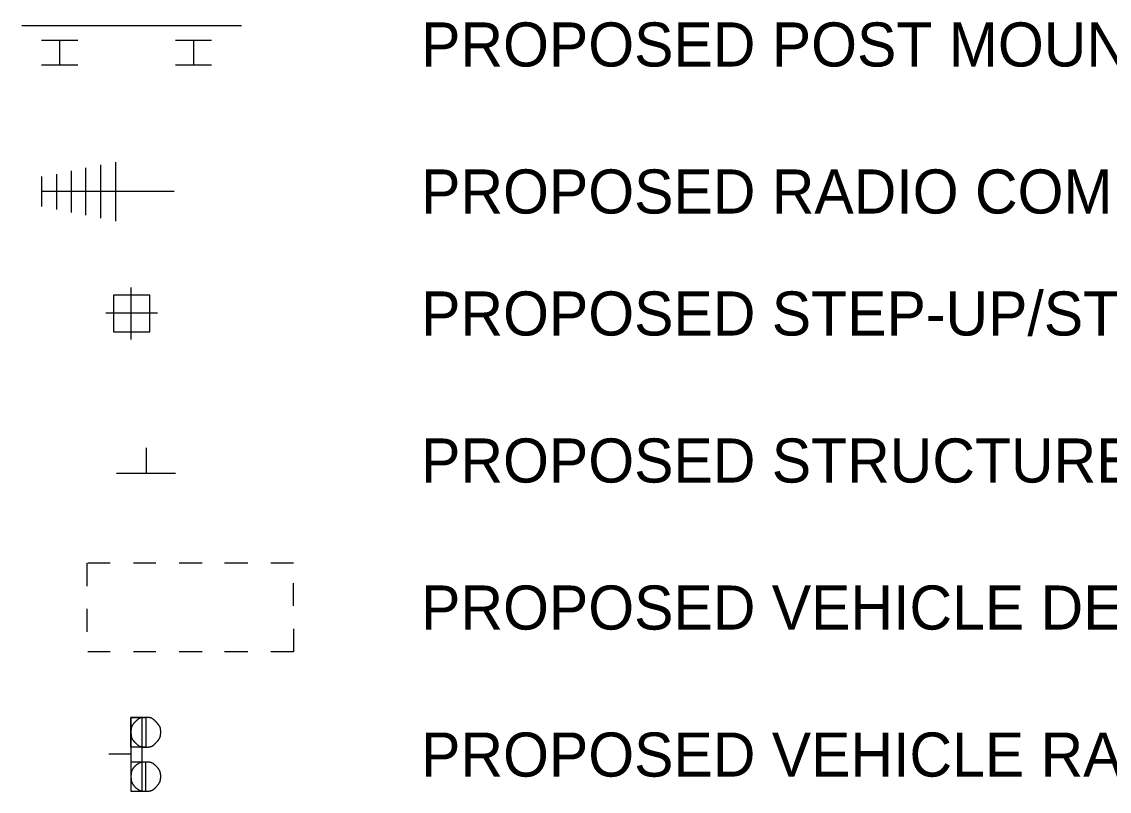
# Model space of a CAD drawing. Extents: x 1299104.8 to 1299141.6, y 239639.8 to 239661.8.
# Drawn here: x 1299113.684 to 1299116.643, y 239651.943 to 239654.037 of the extents above; entities that cross this region are included whole.
import ezdxf

# ---------------------------------------------------------------- set-up
doc = ezdxf.new("R2010")
doc.units = 0
for name, color, linetype in [('DIM TXT', 7, 'Continuous'), ('PDF2_Geometry', 7, 'Continuous'), ('PDF2_Solid Fills', 7, 'Continuous'), ('PDF3_Geometry', 7, 'Continuous'), ('PDF_LEGEND', 7, 'Continuous')]:
    doc.layers.add(name, color=color, linetype=linetype)

msp = doc.modelspace()

# ---------------------------------------------------------------- linework, layer by layer
at = {"layer": 'PDF2_Geometry'}
for points in [[(1299113.858, 239653.6389), (1299113.858, 239653.5105)], [(1299113.8985, 239653.6473), (1299113.8985, 239653.5022)], [(1299113.9389, 239653.6543), (1299113.9389, 239653.4938)], [(1299113.738, 239653.6152), (1299113.738, 239653.5343)], [(1299113.7785, 239653.6222), (1299113.7785, 239653.5259)], [(1299113.8189, 239653.6305), (1299113.8189, 239653.5175)], [(1299114.0994, 239653.5747), (1299113.738, 239653.5747)], [(1299114.0231, 239652.8777), (1299114.0231, 239652.8079)], [(1299114.1026, 239652.8079), (1299113.9422, 239652.8079)], [(1299113.8609, 239652.5634), (1299113.8609, 239652.5007)], [(1299113.9251, 239652.5634), (1299113.8637, 239652.5634)], [(1299114.0493, 239652.5634), (1299113.9879, 239652.5634)], [(1299114.1749, 239652.5634), (1299114.1121, 239652.5634)], [(1299114.2991, 239652.5634), (1299114.2363, 239652.5634)], [(1299114.4232, 239652.5634), (1299114.3618, 239652.5634)], [(1299114.4232, 239652.4476), (1299114.4232, 239652.509)], [(1299113.8609, 239652.4393), (1299113.8609, 239652.3765)], [(1299114.4232, 239652.3848), (1299114.4232, 239652.3221), (1299114.3618, 239652.3221)], [(1299113.9251, 239652.3221), (1299113.8637, 239652.3221)], [(1299114.0493, 239652.3221), (1299113.9879, 239652.3221)], [(1299114.1749, 239652.3221), (1299114.1121, 239652.3221)], [(1299114.2991, 239652.3221), (1299114.2363, 239652.3221)], [(1299113.9814, 239652.1439), (1299114.0121, 239652.1439)], [(1299113.9814, 239652.0435), (1299113.9214, 239652.0435)]]:
    msp.add_lwpolyline(points, dxfattribs=at)
for points in [[(1299113.9926, 239652.1314), (1299113.9856, 239652.1244), (1299113.9814, 239652.1146), (1299113.9814, 239652.1034)], [(1299114.0219, 239652.1439), (1299114.0107, 239652.1439), (1299114.001, 239652.1397), (1299113.9926, 239652.1314)], [(1299114.0498, 239652.1314), (1299114.0428, 239652.1397), (1299114.0317, 239652.1439), (1299114.0219, 239652.1439)], [(1299114.0624, 239652.1034), (1299114.0624, 239652.1146), (1299114.0568, 239652.1244), (1299114.0498, 239652.1314)], [(1299113.9814, 239652.1034), (1299113.9814, 239652.0923), (1299113.9856, 239652.0825), (1299113.9926, 239652.0755)], [(1299114.0498, 239652.0755), (1299114.0568, 239652.0825), (1299114.0624, 239652.0923), (1299114.0624, 239652.1034)], [(1299113.9926, 239652.0755), (1299114.001, 239652.0672), (1299114.0107, 239652.063), (1299114.0219, 239652.063)], [(1299114.0219, 239652.063), (1299114.0317, 239652.063), (1299114.0428, 239652.0672), (1299114.0498, 239652.0755)], [(1299113.9926, 239652.0114), (1299113.9856, 239652.0044), (1299113.9814, 239651.9932), (1299113.9814, 239651.9835)], [(1299114.0219, 239652.0225), (1299114.0107, 239652.0225), (1299114.001, 239652.0183), (1299113.9926, 239652.0114)], [(1299114.0498, 239652.0114), (1299114.0428, 239652.0183), (1299114.0317, 239652.0225), (1299114.0219, 239652.0225)], [(1299114.0624, 239651.9835), (1299114.0624, 239651.9932), (1299114.0568, 239652.0044), (1299114.0498, 239652.0114)], [(1299113.9814, 239651.9835), (1299113.9814, 239651.9723), (1299113.9856, 239651.9625), (1299113.9926, 239651.9542)], [(1299114.0498, 239651.9542), (1299114.0568, 239651.9625), (1299114.0624, 239651.9723), (1299114.0624, 239651.9835)], [(1299113.9926, 239651.9542), (1299114.001, 239651.9472), (1299114.0107, 239651.943), (1299114.0219, 239651.943)], [(1299114.0219, 239651.943), (1299114.0317, 239651.943), (1299114.0428, 239651.9472), (1299114.0498, 239651.9542)]]:
    msp.add_open_spline(points, degree=2, dxfattribs=at)
at = {"layer": 'PDF2_Solid Fills'}
for points in [[(1299113.9814, 239651.943), (1299114.0121, 239651.943), (1299114.0121, 239652.1439), (1299113.9814, 239652.1439)], [(1299114.0219, 239652.063), (1299113.9814, 239652.063), (1299113.9814, 239652.1439), (1299114.0219, 239652.1439)], [(1299114.0219, 239652.0225), (1299113.9814, 239652.0225), (1299113.9814, 239651.943), (1299114.0219, 239651.943)]]:
    msp.add_lwpolyline(points, close=True, dxfattribs=at)
at = {"layer": 'PDF3_Geometry'}
for points in [[(1299113.9824, 239653.1723), (1299113.9824, 239653.3132)], [(1299114.0536, 239653.2435), (1299113.9127, 239653.2435)]]:
    msp.add_lwpolyline(points, dxfattribs=at)
msp.add_lwpolyline([(1299113.9336, 239653.1932), (1299114.0327, 239653.1932), (1299114.0327, 239653.2923), (1299113.9336, 239653.2923)], close=True, dxfattribs=at)
at = {"layer": 'PDF_LEGEND'}
for p, q in [((1299113.6843, 239654.0266), (1299114.282, 239654.0266)), ((1299113.7383, 239653.9863), (1299113.8365, 239653.9863)), ((1299113.7874, 239653.9863), (1299113.7874, 239653.9196)), ((1299114.1026, 239653.9863), (1299114.2009, 239653.9863)), ((1299114.1518, 239653.9863), (1299114.1518, 239653.9196)), ((1299113.7383, 239653.9196), (1299113.8365, 239653.9196)), ((1299114.1026, 239653.9196), (1299114.2009, 239653.9196))]:
    msp.add_line(p, q, dxfattribs=at)

# ---------------------------------------------------------------- texts
at = {"layer": 'DIM TXT'}
for s, p in [('PROPOSED POST MOUNTED SIGN, TYPE A', (1299114.7708, 239653.9147)), ('PROPOSED RADIO COMMUNICATION ANTENNA', (1299114.7708, 239653.5147)), ('PROPOSED STEP-UP/STEP DOWN TRANSFORMER', (1299114.7708, 239653.1828)), ('PROPOSED STRUCTURE MOUNTED SIGN', (1299114.7708, 239652.7828)), ('PROPOSED VEHICLE DETECTOR ZONE', (1299114.7708, 239652.3828)), ('PROPOSED VEHICLE RADAR DETECTOR', (1299114.7708, 239651.9828))]:
    msp.add_text(s, height=0.12, dxfattribs=at).set_placement(p)

doc.saveas('drawing.dxf')
